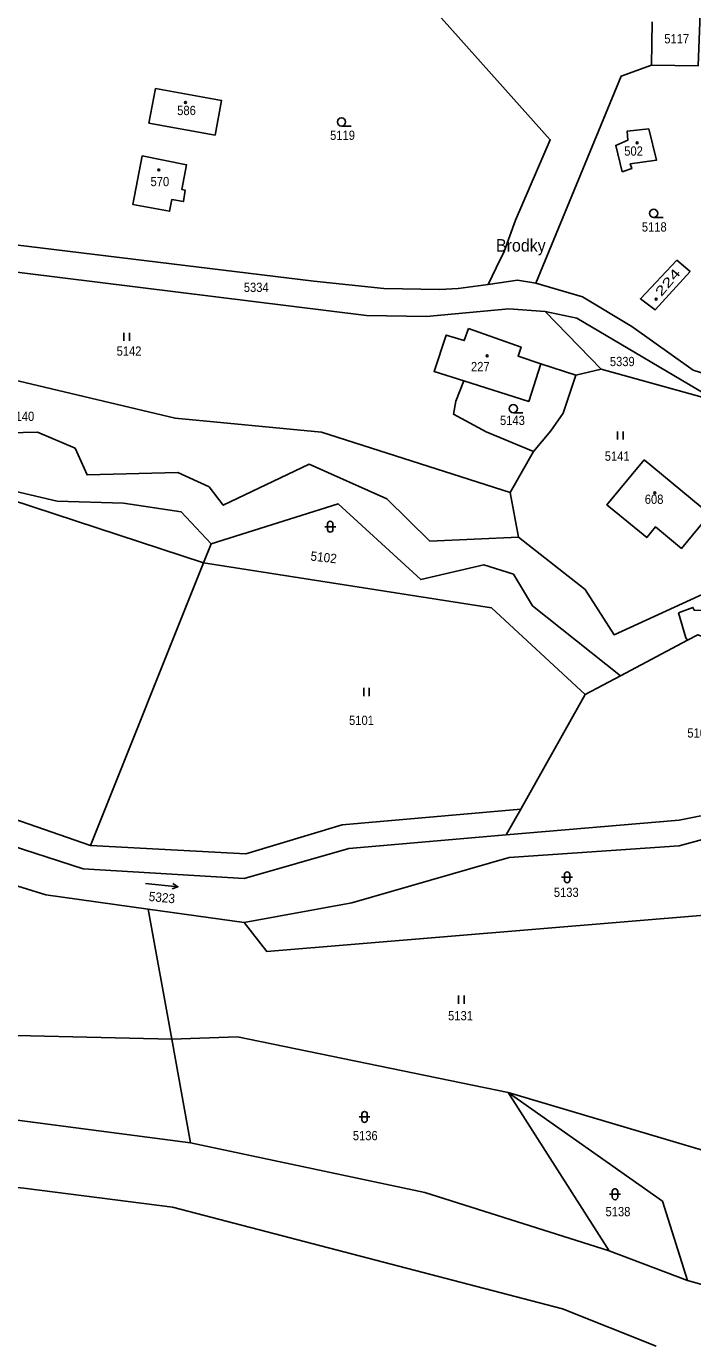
# Model space of a CAD drawing. Extents: x -665688 to -664583, y -1006118 to -1004927.
# Drawn here: x -664897.5 to -664775.4, y -1005645.6 to -1005404.2 of the extents above; entities that cross this region are included whole.
import ezdxf
from ezdxf.enums import TextEntityAlignment as Align

# ---------------------------------------------------------------- set-up
doc = ezdxf.new("R2010")
doc.units = 0
doc.header["$LTSCALE"] = 0.68
doc.layers.add('1', color=7, linetype='Continuous', lineweight=25)
doc.layers.add('25', color=7, linetype='Continuous', lineweight=25)
for name, color, linetype in [('15', 7, 'Continuous'), ('18', 7, 'Continuous'), ('19', 7, 'Continuous')]:
    doc.layers.add(name, color=color, linetype=linetype)

msp = doc.modelspace()

# ---------------------------------------------------------------- linework, layer by layer
at = {"layer": '1'}
for p, q in [((-664863.59, -1005498.93), (-664865, -1005502.46)), ((-664865, -1005502.46), (-664885.68, -1005554.21)), ((-664776.37, -1005516.62), (-664788.63, -1005523.13))]:
    msp.add_line(p, q, dxfattribs=at)
for points in [[(-664812.89, -1005451.45), (-664811.38, -1005448.39), (-664809.91, -1005445.4), (-664807.84, -1005439.72), (-664801.49, -1005424.98), (-664834.73, -1005387.75), (-664840.95, -1005380.66), (-664847.73, -1005373.11)], [(-664774.02, -1005401.84), (-664774.38, -1005411.4), (-664782.97, -1005411.32), (-664782.81, -1005403.35)], [(-664804.12, -1005451.24), (-664788.5, -1005413.32), (-664782.97, -1005411.32)], [(-664812.89, -1005451.45), (-664818.34, -1005452.22), (-664821.75, -1005452.39), (-664832, -1005452.23), (-664844.79, -1005450.86), (-664916.08, -1005442.22), (-664952, -1005436.49)], [(-664958.68, -1005440.16), (-664918.99, -1005446.77), (-664835.18, -1005457.14), (-664824.19, -1005457.34), (-664809.08, -1005455.92), (-664802.4, -1005456.42), (-664792.15, -1005466.99), (-664796.78, -1005468.06), (-664803.23, -1005465.97)], [(-664969.3, -1005446.1), (-664945.43, -1005458.11), (-664870.22, -1005475.95), (-664843.38, -1005478.52), (-664808.84, -1005489.57), (-664807.3, -1005497.72)], [(-664804.12, -1005451.24), (-664807.51, -1005450.69), (-664812.89, -1005451.45)], [(-664765.04, -1005468.16), (-664768.77, -1005469.23), (-664775.33, -1005467.16), (-664786.56, -1005459.19), (-664795.61, -1005453.73), (-664804.12, -1005451.24)], [(-664807.3, -1005497.72), (-664823.52, -1005498.49), (-664831.43, -1005490.72), (-664845.63, -1005484.35), (-664861.39, -1005491.91), (-664864, -1005488.5), (-664869.71, -1005485.89), (-664886.34, -1005486.35), (-664888.54, -1005481.42), (-664895.39, -1005478.51), (-664911.15, -1005478.85), (-664917.14, -1005475.22), (-664920.29, -1005468.16), (-664939.44, -1005469.7), (-664948.5, -1005477.86), (-664952.19, -1005476.3), (-664954.45, -1005466.18), (-664962.99, -1005461.77), (-664976.12, -1005457.02), (-664981.8, -1005452.97)], [(-664865, -1005502.46), (-664927.78, -1005481.87), (-664956.61, -1005485.82), (-664964.51, -1005482.49), (-664972.73, -1005471.31), (-664988.54, -1005462.23), (-664995.99, -1005461.94), (-664985.67, -1005457.24)], [(-664985.67, -1005457.24), (-664975.78, -1005463.7), (-664959.79, -1005470.57), (-664964.6, -1005480.83), (-664955.25, -1005482.24), (-664940.12, -1005481), (-664936.96, -1005474.59), (-664924.8, -1005473.77), (-664915.63, -1005482.78), (-664902.52, -1005484.91), (-664901.73, -1005488.82), (-664891.82, -1005491.12), (-664879.66, -1005491.54), (-664869.11, -1005493.1), (-664863.59, -1005498.93)], [(-664802.4, -1005456.42), (-664796.61, -1005457.63), (-664770.82, -1005472.88), (-664792.15, -1005466.99)], [(-664816.48, -1005459.53), (-664817.24, -1005461.74), (-664820.54, -1005460.74), (-664822.77, -1005467.42), (-664817.35, -1005469.13)], [(-664803.23, -1005465.97), (-664807.4, -1005464.59), (-664806.84, -1005462.92), (-664816.48, -1005459.53)], [(-664817.35, -1005469.13), (-664805.43, -1005472.89), (-664803.23, -1005465.97)], [(-664817.35, -1005469.13), (-664818.77, -1005472.85), (-664819.2, -1005475.22), (-664813.26, -1005478.44), (-664804.54, -1005482.04), (-664808.84, -1005489.57)], [(-664796.78, -1005468.06), (-664799.11, -1005475.05), (-664801.38, -1005478.24), (-664804.54, -1005482.04)], [(-665116, -1005486.34), (-665037.17, -1005561.39), (-665010.92, -1005583.28), (-664991.78, -1005592.85), (-664962.41, -1005603.78), (-664921.71, -1005614.59), (-664897.94, -1005616.96), (-664870.69, -1005620.43), (-664799.26, -1005639.02), (-664782.09, -1005645.9)], [(-664863.59, -1005498.93), (-664840.37, -1005491.62), (-664825.2, -1005505.51), (-664813.63, -1005502.78), (-664808.25, -1005504.49), (-664804.72, -1005510.29), (-664788.63, -1005523.13)], [(-664762.11, -1005504.56), (-664771.39, -1005507.22), (-664789.8, -1005515.61), (-664795.07, -1005507.35), (-664807.3, -1005497.72)], [(-664865, -1005502.46), (-664812.23, -1005510.71), (-664795.07, -1005526.57)], [(-664809.58, -1005552.27), (-664838.4, -1005554.75), (-664857.53, -1005560.23), (-664887.07, -1005558.49), (-664933.48, -1005543.45), (-664952.44, -1005532.63), (-664991.45, -1005525.08), (-665012.03, -1005508)], [(-664990.99, -1005508.78), (-664989.85, -1005519.48), (-664950.5, -1005527.4), (-664931.25, -1005538.39), (-664885.68, -1005554.21)], [(-664746.83, -1005530.12), (-664755.79, -1005541.41), (-664769.9, -1005547.96), (-664777.87, -1005549.55), (-664809.58, -1005552.27), (-664806.9, -1005547.53), (-664795.07, -1005526.57), (-664788.63, -1005523.13)], [(-664875.12, -1005565.84), (-664893.9, -1005563.22), (-664947.17, -1005546.75), (-665000.93, -1005525.33)], [(-664857.56, -1005568.28), (-664837.85, -1005564.71), (-664809.01, -1005556.42), (-664777.88, -1005554.25), (-664768.66, -1005551.79), (-664753.33, -1005544.68), (-664742.26, -1005533.2)], [(-664741.2, -1005543.33), (-664760.39, -1005554.64), (-664771.75, -1005566.81), (-664853.43, -1005573.61), (-664857.56, -1005568.28)], [(-664885.68, -1005554.21), (-664857.27, -1005555.74), (-664839.63, -1005550.42), (-664806.9, -1005547.53)], [(-664867.38, -1005608.64), (-664916.88, -1005602.2), (-664931.13, -1005599.43), (-664964.98, -1005588.84), (-664964.12, -1005586.74), (-664954.79, -1005564.05)], [(-664954.79, -1005564.05), (-664941.98, -1005576.5), (-664912.3, -1005588.7), (-664870.82, -1005589.64), (-664867.38, -1005608.64)], [(-664809.2, -1005599.44), (-664858.81, -1005589.22), (-664870.82, -1005589.64), (-664875.12, -1005565.84), (-664857.56, -1005568.28)], [(-664809.2, -1005599.44), (-664765.6, -1005612.38), (-664755.06, -1005639.78), (-664776.38, -1005633.86)], [(-664790.7, -1005628.4), (-664824.48, -1005617.72), (-664867.38, -1005608.64)]]:
    msp.add_lwpolyline(points, dxfattribs=at)
for points in [[(-664873.8, -1005415.56), (-664861.71, -1005417.77), (-664862.88, -1005424.11), (-664875.01, -1005421.9)], [(-664783.42, -1005422.94), (-664787.43, -1005423.42), (-664787.28, -1005425.07), (-664789.51, -1005426), (-664788.31, -1005430.81), (-664786.57, -1005430.23), (-664786.85, -1005429.35), (-664782, -1005428.69)], [(-664876.25, -1005427.9), (-664868.1, -1005429.53), (-664868.96, -1005434.1), (-664868.35, -1005434.21), (-664868.68, -1005436.29), (-664870.83, -1005435.91), (-664871.21, -1005438.06), (-664877.94, -1005436.83)], [(-664778.31, -1005447.03), (-664784.97, -1005454.08), (-664782.28, -1005456.14), (-664775.89, -1005449.12)], [(-664784.31, -1005483.59), (-664791.1, -1005491.79), (-664783.83, -1005497.81), (-664782.23, -1005495.87), (-664777.47, -1005499.81), (-664772.24, -1005493.54)], [(-664778.03, -1005511.58), (-664776.64, -1005516.17), (-664776.37, -1005516.62), (-664774.44, -1005515.6), (-664765.82, -1005518.88), (-664764.8, -1005516.35), (-664763.65, -1005515.05), (-664758.83, -1005517.16), (-664758.59, -1005516.71), (-664769.79, -1005511.58), (-664770.15, -1005511.46), (-664771.06, -1005510.81), (-664771.29, -1005510.91), (-664771.4, -1005510.73), (-664771.84, -1005511.25), (-664775.14, -1005511.1), (-664775.37, -1005510.61)], [(-664809.2, -1005599.44), (-664780.95, -1005619.34), (-664776.38, -1005633.86), (-664790.7, -1005628.4)]]:
    msp.add_lwpolyline(points, close=True, dxfattribs=at)
at = {"layer": '25'}
for p, q in [((-664839.74, -1005422.45), (-664837.99, -1005422.45)), ((-664782.55, -1005439.19), (-664780.8, -1005439.19)), ((-664879.597, -1005461.795), (-664879.597, -1005460.295)), ((-664878.563, -1005461.795), (-664878.563, -1005460.295)), ((-664808.25, -1005474.95), (-664806.5, -1005474.95)), ((-664789.197, -1005479.865), (-664789.197, -1005478.365)), ((-664788.163, -1005479.865), (-664788.163, -1005478.365)), ((-664842.79, -1005495.82), (-664840.79, -1005495.82)), ((-664842.29, -1005496.32), (-664842.29, -1005495.32)), ((-664841.29, -1005495.32), (-664841.29, -1005496.32)), ((-664835.667, -1005526.845), (-664835.667, -1005525.345)), ((-664834.633, -1005526.845), (-664834.633, -1005525.345)), ((-664875.653, -1005561.132), (-664869.687, -1005561.768)), ((-664799.41, -1005560.03), (-664797.41, -1005560.03)), ((-664798.91, -1005560.53), (-664798.91, -1005559.53)), ((-664797.91, -1005559.53), (-664797.91, -1005560.53)), ((-664818.317, -1005583.165), (-664818.317, -1005581.665)), ((-664817.283, -1005583.165), (-664817.283, -1005581.665)), ((-664836.51, -1005603.91), (-664834.51, -1005603.91)), ((-664836.01, -1005604.41), (-664836.01, -1005603.41)), ((-664835.01, -1005603.41), (-664835.01, -1005604.41)), ((-664790.63, -1005618.06), (-664788.63, -1005618.06)), ((-664790.13, -1005618.56), (-664790.13, -1005617.56)), ((-664789.13, -1005617.56), (-664789.13, -1005618.56))]:
    msp.add_line(p, q, dxfattribs=at)
msp.add_lwpolyline([(-664870.629, -1005561.166), (-664869.687, -1005561.768), (-664870.735, -1005562.159)], dxfattribs=at)
for centre, radius in [((-664868.32, -1005418.14), 0.175), ((-664839.74, -1005421.7), 0.75), ((-664785.58, -1005425.52), 0.175), ((-664873.2, -1005430.5), 0.175), ((-664782.55, -1005438.44), 0.75), ((-664782.1, -1005454.16), 0.175), ((-664813.05, -1005464.52), 0.175), ((-664808.25, -1005474.2), 0.75), ((-664782.34, -1005489.62), 0.174)]:
    msp.add_circle(centre, radius, dxfattribs=at)
for centre, start, end in [((-664841.79, -1005495.32), 0.101, 180.00143), ((-664841.79, -1005496.32), 180.10243, 0.00286), ((-664798.41, -1005559.53), 0.101, 180.00143), ((-664798.41, -1005560.53), 180.10243, 0.00286), ((-664835.51, -1005603.41), 0.101, 180.00143), ((-664835.51, -1005604.41), 180.10243, 0.00286), ((-664789.63, -1005617.56), 0.101, 180.00143), ((-664789.63, -1005618.56), 180.10243, 0.00286)]:
    msp.add_arc(centre, 0.5, start, end, dxfattribs=at)

# ---------------------------------------------------------------- texts
at = {"layer": '15', "width": 0.95}
msp.add_text('Brodky', height=2.3, dxfattribs=at).set_placement((-664806.8795, -1005445.46), align=Align.CENTER)
at = {"layer": '18', "width": 0.9}
for s, p in [('5117', (-664778.3295, -1005407.32)), ('5119', (-664839.5395, -1005424.99)), ('5118', (-664782.4395, -1005441.78)), ('5334', (-664855.3495, -1005452.84)), ('5142', (-664878.6495, -1005464.51)), ('5339', (-664788.2995, -1005466.42)), ('5140', (-664898.2895, -1005476.46)), ('5143', (-664808.4195, -1005477.2)), ('5141', (-664789.2295, -1005483.75)), ('5101', (-664836.0695, -1005532.12)), ('5103', (-664774.1095, -1005534.44)), ('5133', (-664798.5595, -1005563.62)), ('5131', (-664817.9295, -1005586.22)), ('5136', (-664835.3795, -1005608.17)), ('5138', (-664789.0895, -1005622.09))]:
    msp.add_text(s, height=1.7, dxfattribs=at).set_placement(p, align=Align.CENTER)
at = {"layer": '18', "width": 0.95}
for s, rotation, p in [('5102', 353.603, (-664843.0872, -1005502.2742)), ('5323', 354.403, (-664872.7044, -1005564.5686))]:
    msp.add_text(s, height=1.7, rotation=rotation, dxfattribs=at).set_placement(p, align=Align.CENTER)
at = {"layer": '19', "width": 0.9}
for s, p in [('586', (-664868.1195, -1005420.45)), ('570', (-664872.9995, -1005433.47)), ('608', (-664782.4695, -1005491.64))]:
    msp.add_text(s, height=1.7, dxfattribs=at).set_placement(p, align=Align.CENTER)
for s, p in [('502', (-664787.94, -1005427.88)), ('227', (-664816.01, -1005467.35))]:
    msp.add_text(s, height=1.7, dxfattribs=at).set_placement(p)
at = {"layer": '19', "width": 1.5}
msp.add_text('224', height=1.7, rotation=50, dxfattribs=at).set_placement((-664781.144, -1005453.799))

doc.saveas('drawing.dxf')
